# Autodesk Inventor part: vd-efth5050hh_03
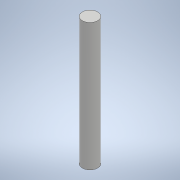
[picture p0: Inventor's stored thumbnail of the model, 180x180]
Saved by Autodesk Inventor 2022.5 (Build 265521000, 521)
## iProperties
Created: 2019-12
Part Number: vd-efth5050hh_03
Material: 一般
Document SubType Name: Modeling
Designer: ImaoCorp
Density: 1 g/cm^3
Appearance: 既定
Author: ImaoCorp
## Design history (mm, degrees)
feature "vd-efth5050hh_03"
node "ソリッド1"
